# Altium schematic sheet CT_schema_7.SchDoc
size 274 x 160 mm
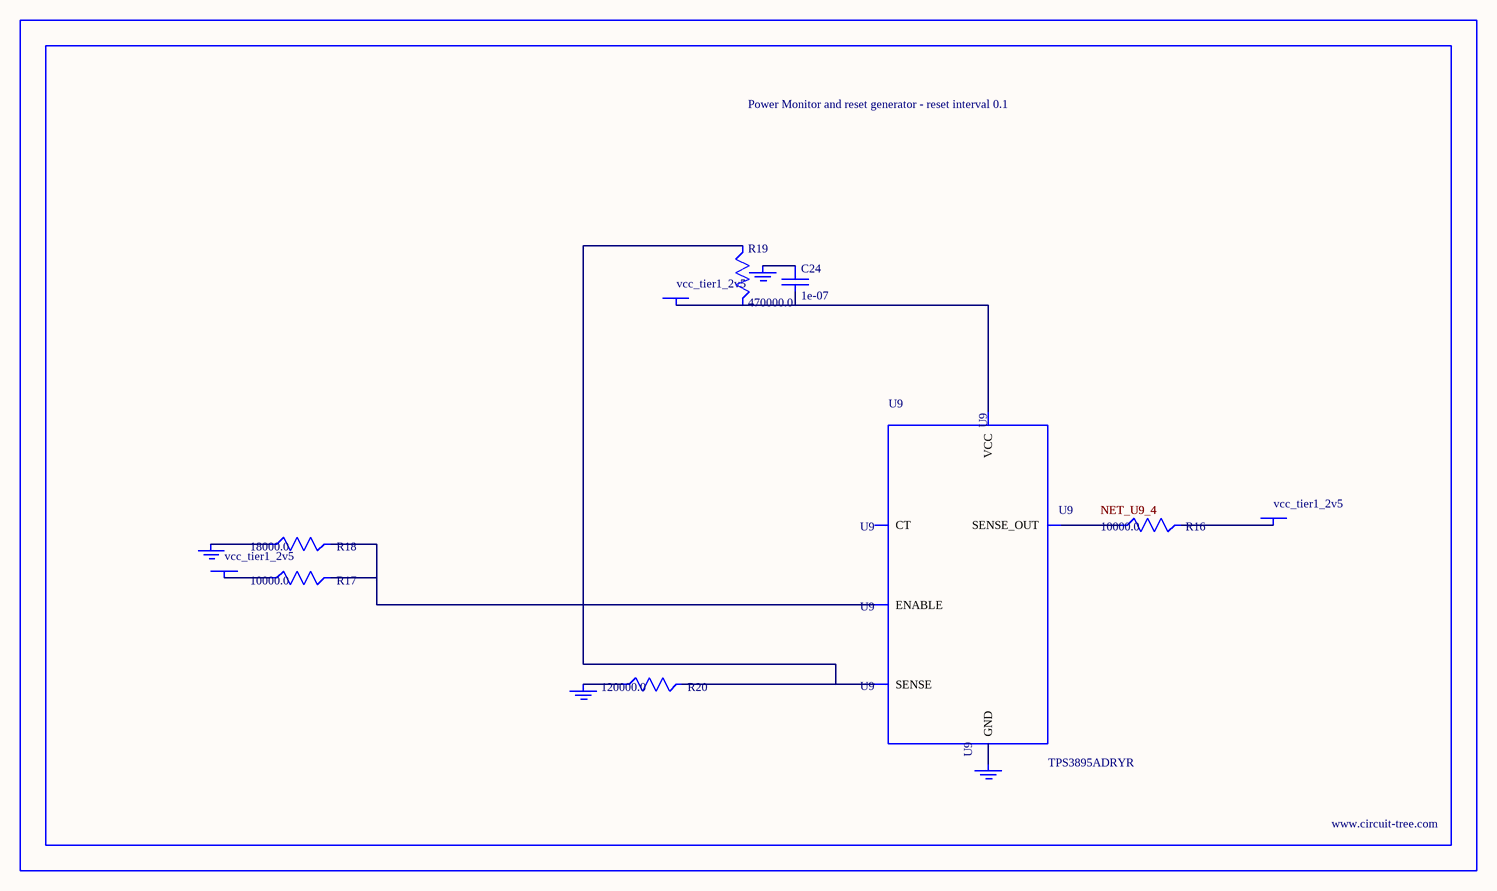
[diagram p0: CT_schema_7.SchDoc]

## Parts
BORDER6  (no value)
C24  1e-07  [C0402]
GND_INSTANCE_6_0  (no value)
GND_INSTANCE_6_1  (no value)
GND_INSTANCE_6_2  (no value)
GND_INSTANCE_6_3  (no value)
POWER_INSTANCE_6_0  vcc_tier1_2v5
POWER_INSTANCE_6_1  vcc_tier1_2v5
POWER_INSTANCE_6_2  vcc_tier1_2v5
R16  10000.0  [R0603]
R17  10000.0  [R0603]
R18  18000.0  [R0603]
R19  470000.0  [R0603]
R20  120000.0  [R0603]
U9  TPS3895ADRYR  [SON-6]

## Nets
NetC24_1: C24.1 GND_INSTANCE_6_2.0(GND)
NetC24_2: C24.2 POWER_INSTANCE_6_2.0(PWR) R19.2 U9.6(VCC)
NetGND_INSTANCE_6_0_0: GND_INSTANCE_6_0.0(GND) R18.1
NetGND_INSTANCE_6_1_0: GND_INSTANCE_6_1.0(GND) R20.1
NetGND_INSTANCE_6_3_0: GND_INSTANCE_6_3.0(GND) U9.2(GND)
NetPOWER_INSTANCE_6_0_0: POWER_INSTANCE_6_0.0(PWR) R17.1
NetPOWER_INSTANCE_6_1_0: POWER_INSTANCE_6_1.0(PWR) R16.2
NetR16_1: R16.1 U9.4(SENSE_OUT)
NetR17_2: R17.2 R18.2 U9.1(ENABLE)
NetR19_1: R19.1 R20.2 U9.3(SENSE)

Not connected (* = marked no-connect by the designer): U9 5(CT)

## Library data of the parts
BORDER6 = BORDER_PAGE6
C24 = C0402C104K3RACTU
GND_INSTANCE_6_0-GND_INSTANCE_6_3 = GND
POWER_INSTANCE_6_0-POWER_INSTANCE_6_2 = PWR
R16 R17 = RC0603JR-0710KL
R18 = RC0603JR-0718KL
R19 = RC0603JR-07470KL
R20 = RC0603JR-07120KL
